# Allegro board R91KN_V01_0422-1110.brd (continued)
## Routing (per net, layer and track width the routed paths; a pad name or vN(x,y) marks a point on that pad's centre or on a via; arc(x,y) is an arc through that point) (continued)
DDC2CLK: length 76.6
  TOP w0.1: U1.AC11 84.95,63.49 v1(85.19,63.73)
  TOP w0.11: v1(72.44,76.25) 72.18,76.5 69.24,76.5 68.61,77.14 67.34,77.14 66.33,78.15 44.13,78.15 35.03,87.25 27.75,87.25 26.15,88.85 25.9,88.85 24.29,87.24 Q1801.2
  BOTTOM w0.11: v1(85.19,63.73) 85.19,63.68 85.53,63.34 85.77,63.34 85.88,63.45 85.88,66.01 84.84,67.05 84.84,67.71 80.34,72.21 78.18,72.21 73.89,76.5 72.7,76.5 v1(72.44,76.25)
DDC2DATA: length 77.8
  TOP w0.1: U1.AC13 84.95,62.55 v1(85.01,62.61)
  TOP w0.11: Q1802.2 24.26,91.09 27.85,87.5 35.13,87.5 44.23,78.4 66.43,78.4 67.44,77.39 68.71,77.39 69.34,76.75 72.18,76.75 v1(72.44,77.01)
  BOTTOM w0.11: v1(72.44,77.01) 72.7,76.75 73.99,76.75 78.28,72.46 80.44,72.46 85.09,67.82 85.09,67.16 86.13,66.12 86.13,63.35 85.88,63.09 85.5,63.09 v1(85.01,62.61)
DDC3CLK: length 99.9
  TOP w0.1: U1.AD20 84.15,56.16 83.88,56.43 83.88,56.95 83.77,57.05 v1(83.77,57.73)
  TOP w0.11: R1008.2 16.89,23.27 19.09,23.27 v1(19.35,23.53) ; v1(27.55,20.26) 27.81,20 31.24,20 33.78,22.54 33.78,27.03 48.4,41.65 72.29,41.65 73.95,43.32 73.95,43.49 v1(73.74,43.7)
  L3_INNER w0.11: v1(83.77,57.73) 83.78,57.73 84.76,56.74 84.76,56.36 84.5,56.1 81.01,56.1 80.32,55.42 74.97,55.42 72.25,52.7 72.25,46.7 74,44.95 74,43.96 v1(73.74,43.7)
  BOTTOM w0.11: v1(19.35,23.53) 19.61,23.27 20.58,23.27 23.85,20 27.29,20 v1(27.55,20.26)
DDC3DATA: length 100.4
  TOP w0.1: U1.AC20 85.02,56 85.34,56.33 85.34,57.55 v1(85.13,57.77)
  TOP w0.11: v1(27.55,19.49) 27.81,19.75 31.34,19.75 33.96,22.37 34.03,22.54 34.03,26.93 48.5,41.4 72.39,41.4 74.2,43.21 74.2,43.45 74.45,43.7 v1(74.51,43.7) ; R1005.2 16.87,23.02 19.09,23.02 v1(19.35,22.76)
  L3_INNER w0.11: v1(85.13,57.77) 84.8,57.43 84.8,57.06 85.01,56.85 85.01,56.26 84.6,55.85 81.11,55.85 80.43,55.17 75.07,55.17 72.5,52.6 72.5,46.8 74.25,45.05 74.25,43.96 v1(74.51,43.7)
  BOTTOM w0.11: v1(27.55,19.49) 27.29,19.75 23.75,19.75 20.48,23.02 19.61,23.02 v1(19.35,22.76)
DDC5CLK_AUX5P: length 84.7
  TOP w0.1: U1.AE16 83.35,59.14 v1(83.19,58.98)
  TOP w0.11: MJ2501.15 11.61,57.91 11.73,58.04 12.74,58.04 13.68,58.98 14.15,58.98 14.73,58.4 14.73,58.75 14.95,58.98 18.68,58.98 19.4,59.7 19.4,60.5 19.65,60.75 21.41,60.75 R2701.2 22.44,60.77 27.59,60.77 32.88,66.05 60.1,66.05 61.72,67.66 v1(62.08,67.66)
  L3_INNER w0.11: v1(62.08,67.66) 61.72,67.66 61.64,67.58 61.64,66.83 61.85,66.62 64.21,66.62 67.59,63.24 68.53,63.24 73.35,58.42 81.54,58.42 81.71,58.6 82.8,58.6 v1(83.19,58.98)
DDC5DATA_AUX5N: length 85.9
  TOP w0.1: v1(83.85,59) 84.15,59.31 U1.AD16
  TOP w0.11: v1(61.54,68.2) 61.54,67.84 60,66.3 32.77,66.3 27.49,61.02 22.44,61.02 R2703.2 21.37,61 19.55,61 19.15,60.6 19.15,59.8 18.57,59.23 14.95,59.23 14.73,59.45 14.73,59.8 14.15,59.23 13.57,59.23 12.64,58.29 11.73,58.29 11.61,58.41 MJ2501.16
  L3_INNER w0.11: v1(83.85,59) 83.19,58.35 81.82,58.35 81.64,58.17 73.25,58.17 68.43,62.99 67.49,62.99 64.11,66.37 61.75,66.37 61.39,66.73 61.39,67.69 61.54,67.84 v1(61.54,68.2)
DDC6CLK: length 41.2
  TOP w0.1: U1.AC1 84.76,69.99 84.76,73.29 80.35,77.7 75.32,77.7 73.3,79.72 73.3,81.75 71.25,83.8 v3(71.25,85.3) ; R4017.2 v3(72.77,97) R4001.1 ; v3(70.7,89.75) 69.99,89.75 R4071.1
  BOTTOM w0.1: v3(72.77,97) 72.77,95.82 71.35,94.4 71.35,90.4 v3(70.7,89.75) 69.61,88.66 69.61,85.74 70.29,85.06 70.95,85.06 71.19,85.3 v3(71.25,85.3)
DDC6DATA: length 41.1
  TOP w0.1: R4002.1 v3(73.91,97.1) R4018.2 ; v3(70.45,85.6) 70.45,84.2 73.1,81.55 73.1,79.64 75.24,77.5 80.27,77.5 84.55,73.22 84.55,69.72 84.95,69.33 U1.AC3 ; v3(70.65,88.5) 70.35,88.5 69.94,88.91 R4070.1
  BOTTOM w0.1: v3(73.91,97.1) 73.91,95.63 71.68,93.39 71.68,89.53 v3(70.65,88.5) 70.65,86.22 70.45,86.03 v3(70.45,85.6)
DDCCLK_DAC1_R: length 7.4
  TOP w0.1: J1601.6 10.74,23.89 11.45,24.6 13.45,24.6 13.98,24.07 D1004.1 R1009.2
DDCCLK_DAC2_R: length 14.3
  TOP w0.1: MJ1001.15 11.13,88.22 12.81,89.9 14.86,89.9 R2009.2
DDCDATA_DAC1_R: length 7.5
  TOP w0.1: J1601.7 9.96,23.2 13.45,23.2 13.98,22.68 D1003.1 R1006.2
DDCDATA_DAC2_R: length 17.7
  TOP w0.1: v3(9.45,86.2) 12.85,89.6 R2006.2
  BOTTOM w0.1: v3(9.45,86.2) 4.61,81.36 MJ1001.12
DPA_0N: length 10.5
  TOP w0.11: C4404.2 21.98,75.22 21.22,75.22 20.97,75.47 20.4,75.47 20.27,75.6 D4401.7 D4401.4 18.43,75.6 18.3,75.47 17.87,75.47 16.69,76.66 16.69,77.14 15.82,78.01 15.4,78.01 15.03,78.38 J2501.3
DPA_0P: length 10.5
  TOP w0.11: C4403.2 21.98,74.97 21.12,74.97 20.87,75.22 20.4,75.22 20.27,75.1 D4401.6 D4401.5 18.43,75.1 18.3,75.22 17.77,75.22 16.44,76.55 16.44,77.04 15.72,77.76 15.4,77.76 15.03,77.38 J2501.1
DPA_1N: length 10.2
  TOP w0.11: C4406.2 21.98,77.22 21.07,77.22 20.82,76.97 20.4,76.97 20.27,77.1 D4401.10 D4401.1 18.43,77.1 18.3,76.97 15.77,79.51 15.4,79.51 15.03,79.88 J2501.6
DPA_1P: length 10.2
  TOP w0.11: J2501.4 15.03,78.88 15.4,79.26 15.67,79.26 18.2,76.72 18.3,76.72 18.43,76.6 D4401.2 D4401.9 20.27,76.6 20.4,76.72 20.92,76.72 21.17,76.97 21.98,76.97 C4405.2
DPA_2N: length 9.8
  TOP w0.11: J2501.9 15.03,81.38 15.4,81.01 16.17,81.01 17.71,79.47 18.3,79.47 18.43,79.6 D4402.4 D4402.7 20.27,79.6 20.4,79.47 20.88,79.47 21.13,79.22 21.98,79.22 C4408.2
DPA_2P: length 9.8
  TOP w0.11: J2501.7 15.03,80.38 15.4,80.76 16.07,80.76 17.6,79.22 18.3,79.22 18.43,79.1 D4402.5 D4402.6 20.27,79.1 20.4,79.22 20.78,79.22 21.03,78.97 21.98,78.97 C4407.2
DPA_3N: length 9.8
  TOP w0.11: J2501.12 15.03,82.88 15.4,82.51 15.99,82.51 17.53,80.97 18.3,80.97 18.43,81.1 D4402.1 D4402.10 20.27,81.1 20.4,80.97 20.62,80.97 20.87,81.22 21.98,81.22 C4410.2
DPA_3P: length 9.8
  TOP w0.11: C4409.2 21.98,80.97 20.98,80.97 20.73,80.72 20.4,80.72 20.27,80.6 D4402.9 D4402.2 18.43,80.6 18.3,80.72 17.42,80.72 15.89,82.26 15.4,82.26 15.03,81.88 J2501.10
DPA_A0N: length 60
  TOP w0.11: U1.AK1 80.03,69.92 80.03,70.44 79.45,71.02 78.88,71.02 78.75,71.15 78.75,71.3 78.62,71.42 78.44,71.42 78.31,71.3 78.31,71.15 78.18,71.02 77.47,71.02 77.04,71.45 71.88,71.45 71.07,72.26 27.53,72.26 24.57,75.22 23.72,75.22 C4404.1
DPA_A0P: length 60
  TOP w0.11: U1.AK3 79.78,69.37 79.78,70.33 79.35,70.77 77.37,70.77 76.93,71.2 71.78,71.2 70.97,72.01 27.43,72.01 24.47,74.97 23.72,74.97 C4403.1
DPA_A1N: length 61.9
  TOP w0.11: C4406.1 23.72,77.22 24.78,77.22 28.76,73.25 78.52,73.25 79.38,72.39 79.56,72.39 79.64,72.47 79.82,72.47 79.95,72.35 79.95,72.16 79.87,72.08 79.87,71.9 80.89,70.87 80.89,69.86 U1.AH1
DPA_A1P: length 61.9
  TOP w0.11: U1.AH3 80.64,69.31 80.64,70.77 78.41,73 28.65,73 24.68,76.97 23.72,76.97 C4405.1
DPA_A2N: length 65.7
  TOP w0.099: 81.81,71.61 81.83,71.6 81.83,71.56 82.25,71.14 82.25,68.71 82.04,68.51 81.84,68.51 81.75,68.42 U1.AG5
  TOP w0.11: 81.81,71.61 79.21,74.21 29.85,74.21 24.84,79.22 23.72,79.22 C4408.1
DPA_A2P: length 65.7
  TOP w0.099: 81.64,71.44 81.66,71.42 81.69,71.42 82.05,71.06 82.05,68.79 81.96,68.71 81.84,68.71 81.75,68.79 U1.AG3
  TOP w0.11: C4407.1 23.72,78.97 24.74,78.97 29.75,73.96 79.11,73.96 80.88,72.2 80.88,72.02 80.68,71.82 80.68,71.64 80.81,71.51 81,71.51 81.19,71.7 81.37,71.7 81.64,71.44
DPA_A3N: length 67.4
  TOP w0.099: U1.AF4 82.55,68.81 82.63,68.89 82.84,68.89 83.05,69.09 83.05,69.98 82.83,70.21 82.83,70.68 82.85,70.71 82.85,70.73
  TOP w0.11: C4410.1 23.72,81.22 24.18,81.22 30.3,75.1 79.94,75.1 82.85,72.19 82.85,70.73
DPA_A3P: length 67.4
  TOP w0.099: U1.AF2 82.55,69.18 82.64,69.09 82.76,69.09 82.85,69.18 82.85,69.9 82.63,70.12 82.63,70.68 82.6,70.71 82.6,70.73
  TOP w0.11: 82.6,70.73 82.6,72.09 82.42,72.26 82.24,72.26 82.06,72.08 81.87,72.08 81.74,72.21 81.74,72.39 81.93,72.57 81.93,72.76 79.83,74.85 30.2,74.85 24.07,80.97 23.72,80.97 C4409.1
DPA_GND: length 9.1
  TOP w0.5: R2715.2 v3(20.35,52.2) ; R2718.2 v3(20.35,55.6) ; R2714.2 v3(20.35,51.2) ; R2716.2 v3(20.35,53.4) ; Q2701.3 21.55,48 20.35,49.2 v3(20.35,50) R2713.2 ; R2719.2 v3(20.35,56.6) ; R2720.2 v3(20.35,57.8) ; R2717.2 v3(20.35,54.4)
DPAB_CALR: length 1.5
  TOP w0.3: U1.AE10 83.35,64.22 v1(82.96,64.62)
  BOTTOM w0.4: R2500.1 83.35,65.01 v1(82.96,64.62)
DPB_0N: length 12
  TOP w0.11: C2531.2 20.68,50.73 19.03,50.73 R2714.1 18.08,50.73 17.62,50.73 17.27,51.08 16.3,51.08 16.17,51.2 D2504.7 D2504.4 14.33,51.2 14.2,51.08 12.93,51.08 12.46,51.54 11.83,51.54 11.45,51.91 MJ2501.3
DPB_0P: length 12
  TOP w0.11: MJ2501.1 11.45,50.91 11.83,51.29 12.36,51.29 12.82,50.83 14.2,50.83 14.33,50.7 D2504.5 D2504.6 16.17,50.7 16.3,50.83 17.17,50.83 17.52,50.48 18.08,50.48 R2713.1 19.03,50.48 20.68,50.48 C2530.2
DPB_1M: length 5.9
  TOP w0.1: J2501.14 17.64,83.88 R2526.1
DPB_1N: length 12
  TOP w0.11: MJ2501.6 11.39,53.41 11.76,53.04 12.77,53.04 13.24,52.58 14.2,52.58 14.33,52.7 D2504.1 D2504.10 16.17,52.7 16.3,52.58 17.3,52.58 17.65,52.92 18.08,52.92 R2716.1 19.03,52.92 20.68,52.92 C2533.2
DPB_1P: length 12
  TOP w0.11: MJ2501.4 11.39,52.41 11.76,52.79 12.67,52.79 13.13,52.33 14.2,52.33 14.33,52.2 D2504.2 D2504.9 16.17,52.2 16.3,52.33 17.4,52.33 17.75,52.67 18.08,52.67 R2715.1 19.03,52.67 20.68,52.67 C2532.2
DPB_2N: length 12.2
  TOP w0.11: MJ2501.9 11.45,54.91 11.83,54.54 12.83,54.54 13.77,55.48 14.2,55.48 14.33,55.6 D2503.4 D2503.7 16.17,55.6 16.3,55.48 17.1,55.48 17.45,55.13 18.08,55.13 R2718.1 19.03,55.12 20.68,55.12 C2536.2
DPB_2P: length 12.2
  TOP w0.11: MJ2501.7 11.45,53.91 11.83,54.29 12.94,54.29 13.87,55.23 14.2,55.23 14.33,55.1 D2503.5 D2503.6 16.17,55.1 16.3,55.23 17,55.23 17.35,54.88 18.08,54.88 R2717.1 19.03,54.88 20.68,54.88 C2534.2
DPB_3N: length 12.2
  TOP w0.11: MJ2501.12 11.45,56.41 11.83,56.04 12.66,56.04 13.59,56.98 14.2,56.98 14.33,57.1 D2503.1 D2503.10 16.17,57.1 16.3,56.98 17,56.98 17.35,57.33 18.08,57.33 R2720.1 19.03,57.32 20.68,57.32 C2538.2
DPB_3P: length 12.2
  TOP w0.11: C2537.2 20.68,57.07 19.03,57.07 R2719.1 18.08,57.08 17.45,57.08 17.1,56.73 16.3,56.73 16.17,56.6 D2503.9 D2503.2 14.33,56.6 14.2,56.73 13.7,56.73 12.76,55.79 11.83,55.79 11.45,55.41 MJ2501.10
DPB_AUXN: length 28
  TOP w0.11: J2501.17 15.03,85.38 15.4,85.01 17.4,85.01 18.1,85.7 18.1,87.6 18.37,87.88 18.6,87.88 18.7,87.88 19.23,88.4 19.23,88 19.35,87.88 21.3,87.88 21.42,88 21.42,89.77 Q1802.3 22.2,90.15 22.45,89.9 22.45,87.2 23.1,86.55 23.85,86.55 24.25,86.15 27.15,86.15 27.58,85.72 29.58,85.72 R2523.2 30.73,85.72 32.18,85.72 C2541.2
DPB_AUXP: length 24
  TOP w0.11: J2501.15 15.05,84.38 15.05,84.4 15.4,84.76 17.51,84.76 18.35,85.6 18.35,87.5 18.48,87.62 18.7,87.62 19.23,87.1 19.23,87.5 19.35,87.62 21.45,87.62 21.81,87.27 Q1801.3 23.75,86.3 24.15,85.9 27.05,85.9 27.48,85.47 29.58,85.47 R2522.1 30.73,85.47 32.18,85.47 C2535.2
DPB_C0N: length 65
  TOP w0.099: 78,66.56 78.03,66.56 78.05,66.53 79.34,66.53 79.63,66.24 79.76,66.24 79.88,66.37 79.88,66.47 U1.AL7
  TOP w0.11: C2531.1 22.42,50.73 25.88,50.73 36.95,61.79 67.41,61.79 71.5,65.89 76.84,65.89 77.51,66.56 78,66.56
DPB_C0P: length 65.1
  TOP w0.099: U1.AK8 79.91,66.04 79.55,66.04 79.26,66.34 78.05,66.34 78.03,66.31 78,66.31
  TOP w0.11: C2530.1 22.42,50.48 25.99,50.48 37.06,61.54 67.51,61.54 71.61,65.64 76.94,65.64 77.61,66.31 78,66.31
DPB_C1N: length 65.5
  TOP w0.099: U1.AH6 80.68,67.13 80.34,67.13 80.26,67.05 80.04,67.05 79.93,67.16 79.91,67.17 79.6,67.17 79.46,67.07 79.38,66.99 78.35,66.99 77.9,67.43 77.57,67.43 77.55,67.46 77.52,67.46
  TOP w0.11: 77.52,67.46 70.89,67.46 66.19,62.76 36.04,62.76 26.2,52.92 22.42,52.92 C2533.1
DPB_C1P: length 65.6
  TOP w0.099: U1.AJ7 80.72,66.77 80.72,66.88 80.67,66.93 80.43,66.93 80.35,66.85 79.96,66.85 79.85,66.96 79.85,66.96 79.83,66.98 79.67,66.98 79.59,66.92 79.46,66.79 78.27,66.79 77.82,67.24 77.57,67.24 77.55,67.21 77.52,67.21
  TOP w0.11: 77.52,67.21 70.99,67.21 66.29,62.51 36.14,62.51 26.31,52.67 22.42,52.67 C2532.1
DPB_C2N: length 64
  TOP w0.099: U1.AM5 79.63,68.2 79.7,68.13 79.7,67.99 79.61,67.9 79.06,67.9 78.87,68.1 78.51,68.1 78.35,68.26 77.77,68.26 77.75,68.29 77.72,68.29
  TOP w0.11: C2536.1 22.42,55.12 26.42,55.12 35.61,64.31 65.2,64.31 69.18,68.29 77.72,68.29
DPB_C2P: length 64
  TOP w0.099: U1.AK6 79.85,67.7 78.98,67.7 78.78,67.9 78.43,67.9 78.26,68.06 77.77,68.06 77.75,68.04 77.72,68.04
  TOP w0.11: 77.72,68.04 69.28,68.04 65.3,64.06 35.71,64.06 26.53,54.88 22.42,54.88 C2534.1
DPB_C3N: length 63.7
  TOP w0.11: C2538.1 22.42,57.32 26.69,57.32 34.87,65.5 64.54,65.5 68.66,69.62 77.98,69.62 78.19,69.42 78.37,69.42 78.55,69.6 78.73,69.6 78.86,69.47 78.86,69.29 78.68,69.11 78.68,68.93 78.84,68.77 79.11,68.77 U1.AM3
DPB_C3P: length 63.8
  TOP w0.11: U1.AK5 79.45,68.52 78.74,68.52 77.88,69.38 68.77,69.38 64.64,65.25 34.97,65.25 26.79,57.07 22.42,57.07 C2537.1
DPB_DONGLE_DET: length 15
  TOP w0.1: J2501.13 15.93,83.38 16.94,82.38 D2502.1 20.02,82.38 R2524.1 24.04,82.61 25.25,81.4 26.15,81.4 Q1804.1
DPCD_CALR: length 21.4
  TOP w0.1: v1(96.5,65.39) 96.5,65.39 96.5,65.39 96.15,65.73 U1.J8
  BOTTOM w0.1: v1(96.5,65.39) 96.54,65.39 96.75,65.6 96.76,65.6 98.37,67.21 98.37,67.38 99.65,68.66 99.65,73.52 99.37,73.8 98.77,73.8 98.25,74.32 98.25,76.78 101.55,80.08 101.55,81.2 101.25,81.5 R298.1
DPE_TX0N: length 70.2
  TOP w0.099: U1.AJ15 80.69,60.06 80.69,59.91 80.59,59.82 80.47,59.82 80.34,59.94 79.98,59.94 79.91,59.87 79.6,59.87 79.5,59.97 77.6,59.97 77.57,59.99 77.55,59.99
  TOP w0.11: 77.55,59.99 77.11,59.99 76.15,59.03 71.82,59.03 69.19,56.4 38.85,56.4 21.88,39.42 20.22,39.42 C1606.1
DPE_TX0P: length 70.2
  TOP w0.099: U1.AH16 80.73,59.62 80.38,59.62 80.26,59.74 80.07,59.74 79.99,59.67 79.52,59.67 79.42,59.77 77.6,59.77 77.57,59.74 77.55,59.74
  TOP w0.11: 77.55,59.74 77.22,59.74 76.25,58.78 71.92,58.78 69.29,56.15 38.95,56.15 21.98,39.17 20.22,39.17 C1605.1
DPE_TX1N: length 70.2
  TOP w0.099: 75.46,58.1 75.49,58.1 75.51,58.08 77.12,58.08 77.92,58.87 79.29,58.87 79.6,59.18 79.93,59.18 U1.AK16
  TOP w0.11: C1604.1 20.22,36.33 20.98,36.33 39.96,55.3 69.45,55.3 72.25,58.1 75.46,58.1
DPE_TX1P: length 70.2
  TOP w0.099: 75.46,57.85 75.49,57.85 75.51,57.88 77.21,57.88 78,58.67 79.37,58.67 79.69,58.98 79.78,58.98 79.91,58.85 79.91,58.76 U1.AL17
  TOP w0.11: C1603.1 20.22,36.08 21.09,36.08 40.06,55.05 69.55,55.05 72.36,57.85 75.46,57.85
DPE_TX2N: length 71.8
  TOP w0.099: 75.34,57.04 75.36,57.04 75.39,57.02 76.85,57.02 78.21,58.38 79.49,58.38 79.62,58.26 79.88,58.26 79.94,58.33 80.36,58.33 80.46,58.22 80.6,58.22 80.7,58.32 80.7,58.45 U1.AJ17
  TOP w0.11: 75.34,57.04 72.38,57.04 69.64,54.3 41.15,54.3 20.92,34.08 20.27,34.08 C1602.1
DPE_TX2P: length 71.7
  TOP w0.099: U1.AH18 80.73,58.02 80.38,58.02 80.28,58.13 80.03,58.13 79.96,58.06 79.54,58.06 79.41,58.18 78.29,58.18 76.93,56.82 75.39,56.82 75.36,56.79 75.34,56.79
  TOP w0.11: 75.34,56.79 72.49,56.79 69.75,54.05 41.25,54.05 21.03,33.83 20.27,33.83 C1601.1
DPE_TXCAN: length 68.7
  TOP w0.099: U1.AK14 79.89,60.74 79.53,60.74 79.32,60.52 79.04,60.52 79.02,60.55 78.99,60.55
  TOP w0.11: 78.99,60.55 77.91,60.55 77.83,60.62 74.36,60.62 73.62,59.89 71.16,59.89 68.92,57.65 37.64,57.65 21.61,41.62 20.22,41.62 C1608.1
DPE_TXCAP: length 68.7
  TOP w0.099: U1.AL15 79.9,60.35 79.9,60.46 79.82,60.54 79.61,60.54 79.4,60.33 79.04,60.33 79.02,60.3 78.99,60.3
  TOP w0.11: C1607.1 20.22,41.38 21.72,41.38 37.74,57.4 69.03,57.4 71.27,59.64 73.73,59.64 74.46,60.38 77.73,60.38 77.8,60.3 78.99,60.3
DPEF_CALR: length 1.9
  TOP w0.3: v1(82.3,57.72) 82.3,58.15 U1.AF17
  BOTTOM w0.3: R1500.1 82.86,58.28 v1(82.3,57.72)
DPEF_GND: length 30.8
  TOP w0.4: v3(18.05,28.7) 18.05,28.7 R1612.1
  TOP w0.5: R1607.1 v3(18.05,40.9) ; v3(18.05,27.5) 18.05,27.5 R1611.1 ; R1614.1 v3(18.05,32.3) ; R1613.1 v3(18.05,31.1) ; Q1601.3 18.08,44.02 18.08,42.13 v3(18.05,42.1) R1608.1 ; R1605.1 v3(18.05,38.7) ; R1601.2 v3(18.05,33.3) ; R1603.1 v3(18.05,35.6) ; R1609.1 v3(18.04,25.3) ; R1610.1 v3(18.04,26.5) ; R1606.1 v3(18.05,39.9) ; R1602.2 v3(18.05,34.6) ; R1604.1 v3(18.05,36.8)
  L3_INNER w0.5: v3(18.04,25.3) v3(18.04,26.5) 18.04,27.49 v3(18.05,27.5) v3(18.05,28.7) v3(18.05,31.1) v3(18.05,32.3) v3(18.05,33.3) v3(18.05,34.6) v3(18.05,35.6) v3(18.05,36.8) v3(18.05,38.7) v3(18.05,39.9) v3(18.05,40.9) v3(18.05,42.1)
DPF_TX3N: length 71
  TOP w0.099: 78.16,56.23 78.19,56.23 78.21,56.2 78.85,56.2 79.18,55.87 79.5,55.87 79.59,55.97 79.92,55.97 U1.AK20
  TOP w0.11: C1614.1 20.22,31.82 21.62,31.82 42.9,53.1 70.29,53.1 71.93,54.73 73.18,54.73 74.67,56.23 78.16,56.23
DPF_TX3P: length 71
  TOP w0.099: U1.AL21 79.91,55.56 79.91,55.65 79.79,55.77 79.67,55.77 79.58,55.67 79.09,55.67 78.77,56 78.21,56 78.19,55.98 78.16,55.98
  TOP w0.11: 78.16,55.98 74.77,55.98 73.28,54.48 72.03,54.48 70.39,52.85 43,52.85 21.73,31.57 20.22,31.57 C1613.1
DPF_TX4N: length 73.1
  TOP w0.099: U1.AJ21 80.67,55.28 80.67,55.14 80.57,55.04 80.44,55.04 80.37,55.12 79.94,55.12 79.87,55.05 79.61,55.05 79.61,55.05 ; 79.2,55.25 79.2,55.25 78.96,55.25 78.69,55.52 78.14,55.52 78.11,55.55 78.09,55.55
  TOP w0.1: 79.61,55.05 79.41,55.25 79.2,55.25
  TOP w0.11: C1612.1 20.22,28.23 20.72,28.23 44.4,51.9 70.83,51.9 72.78,53.84 74.77,53.84 76.47,55.55 78.09,55.55
DPF_TX4P: length 73.1
  TOP w0.099: 78.09,55.3 78.11,55.3 78.14,55.33 78.61,55.33 78.88,55.05 79.2,55.05 79.2,55.05 ; 79.47,54.9 79.49,54.89 79.49,54.89 79.53,54.85 79.7,54.85 79.95,54.85 80.03,54.92 80.28,54.92 80.36,54.84 80.71,54.84 U1.AH22
  TOP w0.1: 79.2,55.05 79.32,55.05 79.47,54.9
  TOP w0.11: C1611.1 20.22,27.98 20.82,27.98 44.5,51.65 70.93,51.65 72.88,53.59 74.87,53.59 76.57,55.3 78.09,55.3
DPF_TX5N: length 72.5
  TOP w0.099: 78.77,54.18 78.79,54.18 78.82,54.15 79.35,54.15 79.55,54.36 79.91,54.36 U1.AK22
  TOP w0.11: 78.77,54.18 76.91,54.18 74.98,52.25 73.18,52.25 71.86,50.93 45.52,50.93 20.62,26.02 20.22,26.02 C1610.1
DPF_TX5P: length 72.5
  TOP w0.099: U1.AL23 79.91,53.96 79.91,54.05 79.8,54.16 79.64,54.16 79.43,53.95 78.82,53.95 78.79,53.93 78.77,53.93
  TOP w0.11: C1609.1 20.22,25.77 20.73,25.77 45.63,50.68 71.96,50.68 73.28,52 75.09,52 77.02,53.93 78.77,53.93
DRAM_RST: length 123.1
  TOP w0.097: U202.T2 138.38,49.03 138.7,49.03 139.03,49.36 139.03,49.44 139.71,50.12 139.71,50.92 139.91,51.13 140.34,51.13 140.52,51.31 140.52,52.72 v1(140.27,52.97) 140.15,53.09 140.15,53.79 140.15,53.89 138.48,55.55 138.48,55.58 138.36,55.7 137.93,55.7 137.18,56.45 137.14,56.45 135.64,57.95 v1(135.64,58.89) 135.59,58.94 135.59,58.94 135.25,59.27 135.25,59.86 135.02,60.09 135.01,60.09 134.75,60.34 134.75,60.44 v1(134.72,60.48) 134.94,60.48 135.15,60.69 135.92,60.69 136.08,60.85 136.38,60.85 v1(136.62,61.1) ; v3(130.78,67.98) 131.08,67.98 131.62,67.43 131.65,67.43 131.93,67.15 131.93,67.06 132.16,66.83 132.5,66.83 132.77,67.1 132.77,67.18 133.37,67.78
  BOTTOM w0.097: v1(140.27,52.97) 140.23,52.97 139.58,53.62 137.7,53.62 137.51,53.44 136.13,53.44 133.31,50.62 133.31,48.87 133.37,48.81 ; v3(130.78,67.98) 130.79,67.98 130.79,68.03 131.01,67.82 131.01,66.95 130.91,66.86 130.91,66.34 130.94,66.31 130.94,65.66 130.72,65.43 130.72,64.81 132.97,62.55 132.97,62.25 133.47,61.76 133.47,61.22 134.02,60.67 134.51,60.67 v1(134.72,60.48) ; U402.T2 138.16,67.61 139.55,66.23 139.55,63.06 137.58,61.09 137.24,61.09 137.08,61.25 136.78,61.25 v1(136.62,61.1)
  BOTTOM w0.1: R3616.1 108.08,85.32 119.45,85.32 v4(120.38,86.25) 120.89,86.77 140.31,86.77 145.25,81.83 145.25,66.5 144.15,65.39 142.5,65.39 141.69,64.59 141.69,61.35 141.18,60.84 141.18,60.78 140.36,59.97 140.35,59.97 139.88,59.5 139.03,59.5 138.42,58.89 v1(135.64,58.89)
DRST: length 27.6
  TOP w0.1: v1(94.95,64.56) 94.59,64.2 U1.L10
  BOTTOM w0.1: v1(94.95,64.56) 95.3,64.21 95.98,64.21 96.07,64.12 96.66,64.12 96.96,64.42 96.96,65.52 98.57,67.13 98.59,67.13 98.59,67.31 99.85,68.58 99.85,73.6 99.45,74 98.85,74 98.45,74.4 98.45,76.7 99.15,77.4 99.75,77.4 101.85,79.5 101.85,82.11 R3600.2 C3600.1 104.24,83.49 R3615.2
DRST_R: length 2
  BOTTOM w0.1: R3616.2 C3608.1 R3615.1
EFTX0M: length 19.9
  TOP w0.099: 5.75,34 5.75,33.98 5.78,33.95 5.78,32.75 5.62,32.6 5.12,32.6 4.93,32.79 J1601.17
  TOP w0.11: 5.75,34 5.75,35.3 10.21,39.76 12.67,39.76 12.79,39.89 D1602.4 D1602.7 14.64,39.89 14.76,39.76 15.24,39.76 15.58,39.42 15.88,39.42 R1606.2 16.83,39.42 18.28,39.42 C1606.2
EFTX0P: length 19.8
  TOP w0.099: 6,34 6,33.98 5.97,33.95 5.97,32.67 5.71,32.4 5.12,32.4 4.93,32.21 J1601.18
  TOP w0.11: C1605.2 18.28,39.17 16.83,39.17 R1605.2 15.88,39.17 15.48,39.17 15.14,39.51 14.76,39.51 14.64,39.39 D1602.6 D1602.5 12.79,39.39 12.67,39.51 10.31,39.51 6,35.2 6,34
EFTX1M: length 15.7
  TOP w0.099: 7.67,33.98 7.67,33.95 7.7,33.93 7.7,32.83 7.46,32.59 7.01,32.59 6.84,32.76 J1601.9
  TOP w0.11: 7.67,33.98 7.67,34.19 9.4,35.93 12.67,35.93 12.79,36.05 D1600.1 D1600.10 14.64,36.05 14.76,35.93 14.98,35.93 15.38,36.33 15.88,36.33 R1604.2 16.83,36.33 18.28,36.33 C1604.2
EFTX1P: length 15.7
  TOP w0.099: J1601.10 6.84,32.19 7.04,32.39 7.54,32.39 7.89,32.74 7.89,33.93 7.92,33.95 7.92,33.98
  TOP w0.11: C1603.2 18.28,36.08 16.83,36.08 R1603.2 15.88,36.08 15.48,36.08 15.08,35.68 14.76,35.68 14.64,35.55 D1600.9 D1600.2 12.79,35.55 12.67,35.68 9.51,35.68 7.92,34.09 7.92,33.98
EFTX2M: length 12
  TOP w0.11: C1602.2 18.23,34.08 16.88,34.08 R1602.1 15.83,34.08 15.48,34.08 15.12,34.43 14.76,34.43 14.64,34.55 D1600.7 D1600.4 12.79,34.55 12.67,34.43 11.98,34.43 10.14,32.59 9.57,32.59 J1601.1
EFTX2P: length 12
  TOP w0.11: J1601.2 9.57,32.34 10.24,32.34 12.08,34.18 12.67,34.18 12.79,34.05 D1600.5 D1600.6 14.64,34.05 14.76,34.18 15.02,34.18 15.37,33.83 15.83,33.83 R1601.1 16.88,33.83 18.25,33.83 18.76,33.32 C1601.2
EFTX3M: length 17.5
  TOP w0.099: 9.04,30.68 9.03,30.68 9,30.65 8.1,30.65 7.7,30.24 7.7,27.12 7.42,26.85 7.03,26.85 6.84,27.04 J1601.12
  TOP w0.11: C1614.2 18.28,31.82 16.83,31.82 R1614.2 15.88,31.82 15.32,31.82 15.03,32.12 14.76,32.12 14.64,32.24 D1603.5 D1603.6 12.79,32.24 12.67,32.12 11.27,32.12 9.83,30.68 9.04,30.68
EFTX3P: length 17.5
  TOP w0.099: 9.04,30.43 9.02,30.43 8.99,30.45 8.18,30.45 7.89,30.16 7.89,27.04 7.5,26.65 7.02,26.65 6.84,26.46 J1601.13
  TOP w0.11: 9.04,30.43 9.93,30.43 11.37,31.87 12.67,31.87 12.79,31.74 D1603.7 D1603.4 14.64,31.74 14.76,31.87 14.93,31.87 15.22,31.57 15.88,31.57 R1613.2 16.83,31.57 18.28,31.57 C1613.2
EFTX4M: length 12.1
  TOP w0.11: C1612.2 18.28,28.23 16.83,28.23 R1612.2 15.88,28.23 15.57,28.23 15.1,27.75 15.1,27.35 14.95,27.2 14.76,27.2 14.64,27.33 D1601.10 D1601.1 12.79,27.33 12.67,27.2 12.4,27.2 11.76,26.57 10.36,26.57 10.06,26.87 9.57,26.87 J1601.4
EFTX4P: length 12.1
  TOP w0.11: C1611.2 18.28,27.98 16.83,27.98 R1611.2 15.88,27.98 15.68,27.98 15.35,27.65 15.35,27.25 15.05,26.95 14.76,26.95 14.64,26.83 D1601.9 D1601.2 12.79,26.83 12.67,26.95 12.5,26.95 11.87,26.32 10.26,26.32 9.96,26.62 9.57,26.62 J1601.5
EFTX5M: length 17.2
  TOP w0.099: J1601.20 4.93,27 5.08,26.85 5.67,26.85 5.96,26.55 5.96,25.43 6.45,24.94 9.5,24.94 9.53,24.97 9.55,24.97
  TOP w0.11: C1610.2 18.28,26.02 16.83,26.02 R1610.2 15.88,26.02 15.48,26.02 15.15,25.7 14.76,25.7 14.64,25.83 D1601.7 D1601.4 12.79,25.83 12.67,25.7 10.55,25.7 9.81,24.97 9.55,24.97
EFTX5P: length 17.2
  TOP w0.099: 9.55,24.72 9.53,24.72 9.5,24.74 6.37,24.74 5.77,25.35 5.77,26.47 5.58,26.65 5.06,26.65 4.93,26.52 J1601.21
  TOP w0.11: 9.55,24.72 9.92,24.72 10.65,25.45 12.67,25.45 12.79,25.33 D1601.5 D1601.6 14.64,25.33 14.76,25.45 15.26,25.45 15.58,25.77 15.88,25.77 R1609.2 16.83,25.77 18.28,25.77 C1609.2
EFTXCM: length 34.2
  TOP w0.11: J1601.24 4.31,20.7 3.93,20.7 3.41,21.23 3.41,34.42 10.25,41.26 12.67,41.26 12.79,41.39 D1602.1 D1602.10 14.64,41.39 14.76,41.26 15.06,41.26 15.42,41.62 15.88,41.62 R1608.2 16.83,41.62 18.28,41.62 C1608.2
EFTXCP: length 34.3
  TOP w0.11: J1601.23 5.13,21.79 5.13,21.26 4.83,20.95 4.04,20.95 3.66,21.34 3.66,34.32 10.35,41.01 12.67,41.01 12.79,40.89 D1602.2 D1602.9 14.64,40.89 14.76,41.01 15.16,41.01 15.52,41.38 15.88,41.38 R1607.2 16.83,41.38 18.28,41.38 C1607.2
FANOUT_N: length 8.4
  TOP w0.503: 163.55,18.82 JU4001.2 ; JU4001.2 164.31,18.58 ; JU4001.2 165.06,18.82 ; JU4001.2 165.31,19.58 ; JU4001.2 163.88,18.6 ; JU4001.2 165.29,20 ; JU4001.2 163.31,19.58 ; JU4001.2 163.32,19.16
FANOUT_P: length 9.2
  TOP w0.503: 163.31,21.58 JU4001.1 ; JU4001.1 165.31,21.58 ; JU4001.1 165.31,22.08 ; JU4001.1 164.31,22.58 ; JU4001.1 163.31,21.08 ; JU4001.1 165.31,22.58 ; JU4001.1 163.31,22.58 ; JU4001.1 164.81,22.58
G1_PMBUS_C: length 1.4
  TOP w0.1: R597.2 84.35,85.3 TP502.1
G1_PMBUS_D: length 1.3
  TOP w0.1: R596.2 TP501.1
G_DAC2: length 56.7
  TOP w0.155: v3(23.45,22.1) 23.09,22.1 MR1016.2 ; v3(10.35,66.9) C2002.1 R2002.1 9.15,68.29 L2002.1
  BOTTOM w0.155: v3(10.35,66.9) 10.68,66.57 11.05,66.57 11.43,66.19 11.43,64.42 13.58,62.27 13.58,31.17 16.26,28.49 16.26,26.09 17.65,24.7 20.85,24.7 v3(23.45,22.1)
GB_DAC2: length 54.5
  TOP w0.155: MR1028.2 23.64,21.49 v3(23.45,21.3) ; R2028.1 v3(10.34,66)
  BOTTOM w0.155: v3(10.34,66) 10.61,66.27 10.92,66.27 11.13,66.07 11.13,64.3 13.28,62.15 13.28,31.05 15.96,28.37 15.96,25.97 17.53,24.4 20.73,24.4 22.87,22.26 22.87,21.88 v3(23.45,21.3)
GENERICA: length 19.9
  TOP w0.1: v1(84.96,61.38) 84.96,61.38 84.96,61.37 85.01,61.42 85.73,61.42 U1.AB13
  BOTTOM w0.1: v1(84.96,61.38) 84.96,61.38 84.96,61.39 84.4,61.95 84.28,61.95 83.82,62.41 83.82,64.16 84.07,64.41 84.07,66.02 82.94,67.16 82.94,67.79 81.92,68.8 81.26,68.8 78.94,71.12 76.15,71.12 v4(74.68,69.65) 74.68,68.64 R73.2
GENERICB: length 6.3
  TOP w0.1: U1.W8 88.72,66.17 88.87,66.17 v1(88.94,66.24)
  BOTTOM w0.1: R32.2 89.38,69.68 89.38,66.7 88.94,66.26 v1(88.94,66.24)
GENERICC: length 2.8
  TOP w0.1: U1.W9 88.25,65 v1(87.86,65.39)
  BOTTOM w0.1: TP58.1 89.28,64.54 89.1,64.36 88.82,64.36 87.86,65.32 v1(87.86,65.39)
GENERICD: length 2.9
  TOP w0.1: U1.W7 87.89,66.6 v1(87.76,66.47)
  BOTTOM w0.1: v1(87.76,66.47) 87.91,66.62 TP59.1
GENERICE_HPD4: length 125.9
  TOP w0.1: v3(84,72.59) 84.35,72.24 84.35,69.64 84.56,69.43 84.56,66.37 84.38,66.19 83.97,66.19 83.77,65.99 83.77,64.58 U1.AD10 ; v3(60.07,40.77) 48.72,40.77 34.95,27 34.95,22.1 32.25,19.4 v3(32.25,18.4)
  BOTTOM w0.1: Q1602.2 31.05,18.6 R1617.1 32.25,18.29 v3(32.25,18.4) ; v3(60.07,40.77) 60.07,65.68 59.85,65.91 59.85,74.9 64.84,79.89 64.84,84.84 66,86 67.91,86 71.89,82.02 71.89,80.56 71.89,80.23 78.76,73.36 83.24,73.36 v3(84,72.59)
GPIO_0: length 30.6
  TOP w0.1: U1.U6 89.75,67.48 88.94,68.28 88.79,68.34 88.54,68.58 88.54,69.03 88.42,69.16 88.42,69.6 88.98,70.16 88.98,72.33 89.8,73.15 89.8,78.86 R45.2 89.08,81.04 v3(89.08,81.28)
  BOTTOM w0.1: SW4001.1 97.55,89.65 97.55,86 96.15,84.6 91.79,84.6 89.08,81.89 v3(89.08,81.28)
GPIO_1: length 32.9
  TOP w0.1: v1(90.17,64.49) 89.88,64.2 U1.U10
  BOTTOM w0.1: v1(90.17,64.49) 90.17,64.49 90.17,64.49 90.75,65.07 90.75,67.25 90.98,67.48 90.98,72.72 88.11,75.59 88.11,77.01 87.82,77.3 87.82,80.37 88.65,81.2 88.65,81.77 92.41,85.52 93.76,85.52 R46.2 96.44,87.2 96.62,87.38 96.62,88.42 96.12,88.91 SW4001.2
GPIO_2: length 30.8
  TOP w0.1: U1.T10 90.75,64.47 90.15,65.07 v1(90.15,65.25)
  BOTTOM w0.1: v1(90.15,65.25) 90.55,65.65 90.55,66.3 90.27,66.58 90.06,66.58 89.79,66.85 89.79,67.41 90.55,68.17 90.55,72.7 89.23,74.02 89.23,74.19 87.91,75.51 87.91,76.86 87.62,77.15 87.62,78.78 87.23,79.18 87.23,80.06 88.45,81.28 88.45,81.9 92.02,85.47 92.02,86.61 MR47.2 R47.2 92.14,87.64 92.14,89.4 SW4002.1
GPIO_3_SMBDATA: length 111.2
  TOP w0.1: U1.U8 89.35,65.6 89.03,65.6 89.02,65.59 v1(88.92,65.59) ; v3(59.46,39.88) 58.72,39.14 58.72,32.26 58.01,31.55 58.01,21.65 Q1.2 54.66,18.29 R1.2 54.45,16.59 R3.1
  BOTTOM w0.1: v3(59.46,39.88) 59.46,74.8 64.64,79.97 64.64,84.92 65.92,86.2 67.99,86.2 72.09,82.11 72.09,80.47 72.09,80.31 78.83,73.56 83.87,73.56 83.96,73.47 84.82,73.47 87.12,71.17 87.12,70.16 88.42,68.86 88.42,68.33 88.14,68.05 88.14,67.42 88.44,67.12 88.44,65.91 88.77,65.59 v1(88.92,65.59)
GPIO_4_SMBCLK: length 112.6
  TOP w0.1: U1.U7 89.27,66.88 v1(88.91,66.88) ; v3(58.53,39.87) 58.14,39.49 58.14,32.69 57.55,32.1 57.55,23.3 56.6,22.35 53.9,22.35 53.21,21.66 Q2.2 53.21,19.97 R2.2 52.35,17.11 R4.1
  BOTTOM w0.1: v3(58.53,39.87) 58.53,41.26 58.55,41.28 58.55,74.17 64.44,80.06 64.44,85 65.83,86.4 68.08,86.4 72.29,82.19 72.29,80.39 78.92,73.76 83.95,73.76 84.04,73.67 84.78,73.67 84.85,73.74 87.35,71.25 87.35,70.3 89.09,68.56 89.09,67.05 v1(88.91,66.88)
GPIO_5: length 8.5
  TOP w0.1: U1.T9 90.58,65.17 90.58,65.45 90.38,65.65 90.38,65.79 v1(90.04,66.13)
  BOTTOM w0.1: v1(90.04,66.13) 89.57,66.59 89.57,67.48 90.35,68.26 90.35,71.3 89.66,71.99 R54.2
GPIO_6: length 18.9
  TOP w0.1: U1.T8 90.75,66.08 90.26,66.57 90.04,66.57 89.9,66.71 89.9,66.75 89.84,66.81 89.84,66.88 89.32,67.39 89.32,67.62 88.84,68.1 88.63,68.16 88.09,68.7 87.95,68.7 87.78,68.87 87.78,69.78 87.36,70.2 87.36,71 89.6,73.24 89.6,77.53 89.13,78 88.05,78 87.75,78.31 87.75,79.39 MR58.2
GPIO_7: length 33.2
  TOP w0.1: U1.T7 90.85,66.7 90.85,67.52 90.52,67.86 89.67,67.86 89.44,68.09 89.44,68.58 88.91,69.1 88.83,69.1 88.65,69.28 88.65,69.52 89.18,70.05 89.18,72.13 90,72.95 90,80.99 89.18,81.81 80.44,81.81 77.75,84.5 76.11,84.5 MR57.1
GPIO_8_R: length 4.2
  TOP w0.1: MR53.2 R13.2 R53.2 81.1,90.6 81.74,91.23 U2.2
GPIO_8_SO: length 39.4
  TOP w0.1: v3(92.38,81.89) 90.56,83.7 83.85,83.7 83.45,84.1 83.45,86.1 82.65,86.9 79.53,86.9 78.73,87.7 78.73,88.88 R13.1 ; U1.P10 91.95,64.48 91.5,64.93 91.5,65.82 91.45,65.86 91.45,66.01 v1(91.37,66.1)
  BOTTOM w0.1: v1(91.37,66.1) 91.37,66.1 90.99,66.48 90.99,67.21 91.18,67.4 91.18,72.81 89.99,74 89.99,79.78 92.1,81.89 v3(92.38,81.89)
GPIO_9_R: length 5.3
  TOP w0.1: R14.2 89.26,86.3 R44.2 MR44.2 89.55,88.01 89.55,88.57 89.42,88.69 U2.5
GPIO_9_SI: length 19.7
  TOP w0.1: R14.1 93.34,82.61 93.34,77.02 91.82,75.49 91.82,69.8 91.63,69.61 91.63,69.19 92.15,68.67 U1.P4
GPIO_10_R: length 2.1
  TOP w0.1: U2.6 89.51,89.97 89.78,89.69 R15.2
GPIO_10_SCK: length 21.4
  TOP w0.1: U1.P2 92.23,69.48 92.23,75.34 93.83,76.93 93.83,84.87 90.45,88.24 R15.1
GPIO_11: length 24.2
  TOP w0.1: R48.2 96.57,89.33 96.57,87.2 95.43,86.06 95.43,79.5 94.65,78.72 94.65,76.63 93.09,75.07 93.09,70.3 93.25,70.14 93.25,67.7 U1.N6
GPIO_12: length 23
  TOP w0.1: MR50.2 93.34,89.29 93.34,86.76 94.05,86.05 94.05,76.88 92.43,75.26 92.43,69.58 92.63,69.37 92.63,68.87 92.95,68.55 U1.N5
GPIO_13: length 21.9
  TOP w0.1: U1.N3 92.95,69.34 92.63,69.66 92.63,75.18 94.25,76.79 94.25,86.13 94.31,86.2 94.31,89.05 MR49.2
GPIO_14_HPD2: length 90.5
  TOP w0.1: v1(86.56,65) 86.56,65 U1.Y9 ; R2530.1 16.75,72.44 Q2513.2 18.06,69.65 18.69,69.01 19.74,69.01 21.67,70.94 22.48,70.94 23.01,70.41 23.01,69.75 23.77,68.99 24.41,68.99 24.82,68.58 60.88,68.58 v3(62.18,69.88)
  BOTTOM w0.1: v3(62.18,69.88) 62.18,75.18 65.38,78.38 66.17,78.38 67.08,77.47 69.09,77.47 69.77,76.78 71.53,76.78 72.54,77.8 73.63,77.8 78.36,73.08 80.34,73.08 85.34,68.07 85.34,67.34 86.16,66.52 86.16,66.51 86.4,66.28 86.4,66.28 86.56,66.12 v1(86.56,65)
GPIO_15_PWRCNTL_0: length 54.7
  TOP w0.1: U1.N1 92.89,69.86 92.89,75.15 94.45,76.71 94.45,78.8 95.23,79.59 95.23,86.7 95.58,87.05 95.58,89.34 R1240.1 MR1240.2 95.55,90.29 95.55,92.84 94.79,93.6 91.26,93.6 83.56,101.3 v3(76.65,101.3)
  BOTTOM w0.1: Q1200.1 71.43,103.72 73,102.15 75.8,102.15 v3(76.65,101.3)
GPIO_16: length 23.9
  TOP w0.1: U1.M4 94.06,68.92 94.06,69.54 93.95,69.65 93.95,70.38 93.7,70.64 93.7,73.39 94.68,74.37 94.68,75.81 95.25,76.38 95.25,78.47 96.03,79.26 96.03,80.28 98.85,83.09 98.85,89.19 MR55.2
GPIO_17_THERMINT: length 50.3
  TOP w0.1: R4080.1 R4401.2 R4011.2 v3(75.06,96.89) ; v3(72.85,93.6) 72.01,92.76 72.01,89.64 73.01,88.64 73.01,87.54 73.76,86.79 76.21,86.79 80.66,82.35 89.92,82.35 90.22,82.05 90.22,72.89 89.46,72.12 89.46,69.93 89.45,69.92 89.45,69.9 89.41,69.87 89.41,68.91 89.69,68.64 89.78,68.64 90.33,68.08 90.67,68.08 U1.R6
  BOTTOM w0.1: v3(72.85,93.6) 75.06,95.81 v3(75.06,96.89)
GPIO_18_HPD3: length 1.5
  TOP w0.1: v1(87.75,64.7) 87.85,64.7 U1.W10
  BOTTOM w0.1: TP97.1 v1(87.75,64.7)
GPIO_19_CTF: length 53.1
  TOP w0.1: R4400.2 105.88,107.87 106.65,107.1 106.65,106.2 109.14,103.71 109.14,96.1 R4062.1 108.65,94.63 107.7,93.68 106.12,93.68 105.59,94.21 101.67,94.21 100.25,92.78 R4038.1 99.31,92.09 98.84,92.56 98.06,92.56 97.75,92.25 97.75,82.28 95.83,80.36 95.83,79.34 95.05,78.55 95.05,76.46 93.5,74.91 93.5,70.56 93.75,70.3 U1.M2
GPIO_20_PWRCNTL_1: length 52.8
  TOP w0.1: R1241.1 81.91,85.94 81.45,86.4 79.55,86.4 78.35,87.6 78.35,90 77.95,90.4 v3(77.95,100.71) ; MR1241.2 82.97,83.39 90.01,83.39 90.19,83.39 91.9,81.68 91.9,76.45 91.9,76.45 91.9,76.42 91.22,75.74 91.22,70.54 90.84,70.16 90.84,69.59 90.88,69.54 90.88,69.02 91.29,68.61 91.39,68.61 91.66,68.33 91.66,67.42 92.32,66.76 92.32,66.17 U1.P8
  BOTTOM w0.1: Q1201.1 75.43,104.17 77.95,101.65 v3(77.95,100.71)
GPIO_21: length 3.3
  TOP w0.1: v1(91.39,66.82) 91.38,66.82 91.38,66.82 91.6,66.6 U1.P7
  BOTTOM w0.1: TP94.1 91.38,68.53 91.38,67.07 91.39,67.06 91.39,66.92 91.38,66.91 91.38,66.82 v1(91.39,66.82)
GPIO_22_CS: length 38.4
  TOP w0.1: U1.N8 93.15,66.07 92.61,66.61 92.61,68.56 92.09,69.08 92.04,69.08 91.85,69.28 91.85,69.55 92.02,69.72 92.02,75.42 93.63,77.02 93.63,84.32 89.84,88.11 89.84,88.75 89.2,89.38 87.38,89.38 83.46,93.29 80.54,93.29 79.65,92.4 R16.1
GPIO_22_ROMCSB_R: length 3.5
  TOP w0.1: R16.2 R24.1 81.16,91.5 82.17,92.5 U2.1
GPIO_23: length 18.7
  TOP w0.1: U1.N7 93.45,66.9 93.45,70.23 93.29,70.38 93.29,74.99 94.85,76.54 94.85,78.64 95.63,79.42 95.63,82.27 TP91.1
GPU_DMINUS: length 33.7
  TOP w0.125: U1.T2 90.62,69.47 90.62,70.37 90.95,70.7 90.95,75.8 91.69,76.54 91.69,81.59 90.1,83.18 80.97,83.18 76.1,88.05 76.1,88.86 C4004.2 76.05,89.59 76.05,89.95 76.15,90.05 U4001.4
GPU_DPLUS: length 34.6
  TOP w0.1: 90.32,69.77 90.32,69.62 90.23,69.53 90.23,69.28 90.55,68.96 U1.T4
  TOP w0.125: U4001.3 75.65,90.05 75.75,89.95 75.75,89.49 C4004.1 75.8,88.86 75.8,87.93 80.85,82.88 89.97,82.88 91.39,81.47 91.39,76.66 90.65,75.92 90.65,70.82 90.32,70.5 90.32,69.77
HPD1: length 68.7
  TOP w0.1: Q4402.2 24.12,70.19 R4409.1 60.92,70.19 61.59,70.87 70.76,70.87 70.97,70.66 v3(76.5,70.66) ; U1.AC14 84.85,60.8 v1(84.25,61.4)
  BOTTOM w0.1: v3(76.5,70.66) 77.63,70.66 77.88,70.92 78.84,70.92 81.15,68.6 81.84,68.6 82.73,67.71 82.73,67.07 83.87,65.94 83.87,64.5 83.62,64.24 83.62,62.32 84.25,61.69 v1(84.25,61.4)
HPD1_A: length 7.8
  TOP w0.1: R4410.2 16.06,62 15.05,62 14.73,61.67 14.73,61.4 12.75,61.4 11.27,59.91 MJ2501.19
HPD4_IN: length 1.6
  BOTTOM w0.1: Q1602.1 33.09,17.35 R1618.1
HPD_DPB: length 16.7
  TOP w0.1: v3(17.35,85.7) 16.98,86.08 D4405.1 15.86,85.88 J2501.18 ; v3(18.25,74.3) 18.79,73.76 R2527.2
  BOTTOM w0.1: v3(18.25,74.3) 18.25,74.7 17.35,75.6 v3(17.35,85.7)
HPD_DVIEF: length 38.2
  BOTTOM w0.1: J1601.16 4.75,17.99 4.75,16.5 5.26,15.99 5.26,15.29 4.65,14.68 4.65,13.69 5.46,12.88 9.86,12.88 10.92,13.94 11.76,13.94 12.06,13.64 19.69,13.64 20.58,14.53 30.48,14.53 32.26,16.31 R1618.2
JTAG_TCK: length 89.7
  TOP w0.1: v3(89.71,81.91) 89.55,82.07 80.59,82.07 76.15,86.51 73.56,86.51 72.67,87.4 68.92,87.4 v3(66.94,85.41) ; v3(101.75,92.63) 101.75,87.72 v3(100.3,86.28) 100.3,81.99 96.75,78.44 96.75,77.43 94.88,75.56 94.88,74.29 93.93,73.34 93.93,70.69 94.15,70.47 94.15,69.74 94.55,69.34 U1.L3
  BOTTOM w0.1: 101.75,91.08 v3(101.75,92.63) ; v3(66.94,85.41) 65.35,83.83 65.35,79.6 61.04,75.29 61.04,69.47 61.17,69.34 62.55,69.34 63.89,70.67 NR75.2 ; v3(89.71,81.91) 91.59,83.79 97.81,83.79 v3(100.3,86.28)
JTAG_TDI: length 29.9
  TOP w0.1: v3(104.19,92.35) 104.15,92.31 104.15,85.1 97.35,78.3 97.35,77.46 95.28,75.39 95.28,74.13 94.33,73.17 94.33,70.91 94.55,70.69 94.55,70.24 94.87,69.93 94.87,69.66 94.84,69.63 94.84,69.17 94.87,69.13 94.87,68.86 94.55,68.54 U1.L5
  BOTTOM w0.1: v3(104.19,92.35) 104.28,92.26 104.28,91.08
JTAG_TDO: length 29.5
  TOP w0.099: 95.68,70.38 95.64,70.09
  TOP w0.1: U1.K4 95.46,69.07 95.66,69.27 95.66,69.53 95.64,69.6 95.64,69.63 95.64,70.08 95.64,70.09 ; 95.68,70.38 95.68,75.23 97.92,77.47 97.92,78.19 105.55,85.83 105.55,92.04 v3(105.87,92.35)
  BOTTOM w0.1: v3(105.87,92.35) 105.55,92.04 105.55,91.09 105.56,91.08
JTAG_TMS: length 27.7
  TOP w0.1: U1.L1 94.35,70 94.35,70.55 94.13,70.78 94.13,73.25 95.08,74.21 95.08,75.48 96.95,77.35 96.95,78.23 103.02,84.3 v3(103.02,92.35)
  BOTTOM w0.1: v3(103.02,92.35) 103.02,91.08
JTAG_TRSTB: length 29.6
  TOP w0.1: R38.2 R39.1 104.45,90.29 104.45,85.12 97.65,78.32 97.65,77.48 95.48,75.31 95.48,74.04 94.53,73.09 94.53,71.02 94.75,70.79 94.75,70.32 95.06,70.01 95.06,69.57 95.03,69.54 95.03,69.23 95.06,69.19 95.06,68.77 94.87,68.57 94.87,67.72 U1.L6
JTDIO_LOOP: length 8.7
  BOTTOM w0.15: MPCIE1.A7 51.65,5.9 51.8,6.05 51.8,7.05 51.45,7.4 50.92,7.4 50.62,7.1 50.62,3.52 MPCIE1.A6
LDO1_FB: length 5.8
  BOTTOM w0.5: R864.1 R865.2 C865.2 54.84,34.49 54.25,33.9 53.75,33.9 53.07,33.22 U861.7
LDO1_REFIN: length 2
  BOTTOM w0.5: R866.2 50.5,32.59 U861.5
LDO2_FB: length 4.3
  BOTTOM w0.5: U851.7 50.88,43.97 R854.1 52.34,43.69 R855.2 C855.2
LED: length 2.9
  TOP w0.1: D4000.1 Q4050.3
LED_ON: length 1.9
  TOP w0.1: Q4050.1 90.92,97.81 R4058.1
LED_PWR: length 2.4
  TOP w0.1: R4059.1 92.03,106.46 D4000.2
LM63_PWM: length 1.5
  TOP w0.1: U4001.5 77.68,89.49 R4081.1
M_DQMA#0: length 63.2
  TOP w0.1: U1.E32 99.35,47.55
  TOP w0.12: U202.E7 134.18,40.01 134.83,40.01 135.17,40.34 135.17,41.78 ; 99.35,47.55 99.35,47.55 100.61,46.28 100.62,46.28 100.63,46.28 100.97,46.28 100.97,46.28 101.69,46.28 102.33,45.64 102.33,45.38 102.34,45.37 v1(102.34,45.36) ; 134.37,42.86 131.87,42.86 131.13,43.59 129.16,43.59 128.9,43.84 v4(128.42,43.84) 127.57,43.84 125.59,45.83 112.8,45.83 109.49,49.14 105.48,49.14 v1(105.25,48.92)
  TOP w0.13: 135.17,41.78 135.17,42.05 134.37,42.86
  BOTTOM w0.12: v1(102.34,45.36) 102.12,45.36 101.98,45.49 101.98,48.19 101.86,48.3 101.06,48.3 100.94,48.18 100.94,48.05 100.81,47.92 100.23,47.92 100.11,48.05 100.11,49.28 100.01,49.38 99.91,49.38 99.78,49.51 99.78,49.66 100.03,49.9 100.58,49.9 100.7,49.78 100.7,48.98 100.83,48.86 101.06,48.86 101.18,48.98 101.18,49.78 101.3,49.9 101.54,49.9 101.66,49.78 101.66,49.17 101.84,49 102.02,49 102.14,49.12 102.14,49.78 102.26,49.9 102.5,49.9 102.62,49.78 102.62,48.63 102.75,48.51 102.92,48.51 103.05,48.63 103.05,49.77 103.17,49.9 103.37,49.9 103.49,49.77 103.49,48.59 103.62,48.47 103.82,48.47 103.95,48.59 103.95,50.21 104.07,50.34 104.29,50.34 104.41,50.21 104.41,49.22 104.54,49.09 105.13,49.09 105.25,48.97 v1(105.25,48.92)
M_DQMA#1: length 66.4
  TOP w0.12: U1.E30 99.22,49 99.1,48.88 99.1,48.73 99.26,48.56 99.57,48.56 99.7,48.44 99.7,47.74 100.1,47.34 100.1,47.34 100.34,47.09 100.68,47.09 100.69,47.1 101.18,47.1 102.51,45.77 102.75,45.53 102.75,45.19 102.67,45.11 102.67,44.73 102.69,44.72 102.69,44.63 102.58,44.52 101.53,44.52 101.41,44.4 101.41,43.99 101.54,43.87 102.27,43.87 v4(102.32,43.91) 102.37,43.91 102.55,43.73 102.55,43 102.44,42.88 101.55,42.88 101.42,42.76 101.42,42.48 101.55,42.36 102.55,42.36 102.67,42.23 102.67,42 102.55,41.88 101.59,41.88 101.47,41.75 101.47,41.42 101.46,41.42 101.46,39.38 106.39,34.46 106.78,34.46 108.08,33.16 122.65,33.16 124.38,31.43 134.94,31.43 137.96,34.45 138.61,34.45 138.84,34.67 138.84,34.67 139.56,35.38 139.56,35.39 140.12,35.96 140.12,37.23 140.13,37.24 140.13,37.58 139.89,37.82 139.36,37.82 139.16,38.02 138.87,38.02 138.56,38.32 138.56,38.51 138.22,38.86 137.75,38.86 137.4,39.22 137.37,39.22
M_DQMA#2: length 66
  TOP w0.099: U1.A21 100.95,55.4 102.41,55.4 102.48,55.32
  TOP w0.12: 102.48,55.32 104.2,55.32 105.37,54.15 109.55,54.15 112.04,51.66 112.04,50.91 113.48,49.47 114.48,49.47 115.06,48.89 122.66,48.89 123.04,49.27 123.04,49.7 122.88,49.85 122,49.85 121.88,49.98 121.88,50.16 122,50.29 122.88,50.29 v4(123.04,50.46) 123.24,50.46 123.66,50.88 123.97,50.88 v1(124.05,50.79)
  BOTTOM w0.12: v1(124.05,50.79) 123.81,50.79 123.69,50.66 123.69,50.25 123.8,50.13 124.16,50.13 124.18,50.12 124.41,50.12 124.53,50.25 124.53,50.45 124.66,50.58 124.88,50.58 125.01,50.45 125.01,50.19 125.13,50.06 125.35,50.06 125.48,50.19 125.48,50.88 125.35,51 125.04,51 125.03,51.02 124.48,51.02 124.35,51.14 124.35,51.33 124.48,51.45 124.6,51.45 124.73,51.58 124.73,51.75 124.82,51.84 126.26,51.84 126.47,51.63 126.47,50.15 126.69,49.93 126.69,49.76 126.69,49.74 126.69,48.33 126.69,48.31 126.69,47.79 127,47.48 128.42,47.48 128.54,47.35 128.54,46.3 128.42,46.18 127.78,46.18 127.5,46.47 127.06,46.47 126.81,46.22 126.81,46.2 126.39,45.78 126.39,43.31 127.02,42.67 130.88,42.67 131.49,42.06 133.51,42.06 133.72,42.27 133.72,42.47 134.02,42.77 134.43,42.77 134.63,42.56 134.8,42.56 135.07,42.83 135.25,42.83 135.41,42.67 135.41,42.49 135.14,42.22 135.14,42.05 135.31,41.88 135.48,41.88 135.69,42.09 135.86,42.09 136.03,41.92 136.03,41.75 135.82,41.54 135.82,41.38 136.31,40.89 136.31,40.72 136.01,40.43 136.01,40.25 136.17,40.09 136.35,40.09 136.65,40.38 137.32,40.38 137.45,40.26 137.45,40.1 137.37,40.02
M_DQMA#3: length 66.4
  TOP w0.099: 104.58,55.48 104.47,55.6 101.21,55.6 101.09,55.71 100.82,55.71 100.81,55.71 100.8,55.71 100.77,55.69 100.5,55.69 100.22,55.4 U1.C21
  TOP w0.12: 104.58,55.48 105.51,54.55 109.7,54.55 112.44,51.82 112.44,51.07 113.64,49.86 114.91,49.86 115.06,50.01 115.27,50.01 115.38,49.89 115.38,49.41 115.5,49.28 121.84,49.28 v1(121.85,49.3)
  BOTTOM w0.12: v1(121.85,49.3) 121.57,49.02 121.57,48.67 121.34,48.44 121.29,48.44 121.16,48.31 121.16,47.2 121.28,47.08 122.5,47.08 122.73,46.85 122.73,46.72 122.6,46.59 121.28,46.59 121.16,46.48 121.16,46.23 121.28,46.12 123.15,46.12 123.28,45.99 123.28,45.76 123.15,45.63 121.27,45.63 121.16,45.53 121.16,45.29 121.27,45.19 121.61,45.19 v4(121.73,45.06) 121.73,44.94 121.62,44.84 121.62,44.62 121.83,44.42 122,44.42 122.77,45.19 122.95,45.19 123.11,45.03 123.11,44.85 122.34,44.08 122.34,43.91 122.51,43.74 122.68,43.74 123.52,44.58 123.7,44.58 123.86,44.42 123.86,44.24 123.02,43.4 123.02,43.23 123.19,43.06 123.36,43.06 124.25,43.95 124.42,43.95 124.59,43.78 124.59,43.61 123.7,42.72 123.7,42.55 123.87,42.38 124.04,42.38 124.43,42.77 124.6,42.77 124.77,42.61 124.77,42.43 124.37,42.04 124.37,41.87 124.54,41.7 124.71,41.7 125.1,42.09 125.25,42.09 125.44,41.9 125.44,41.75 125.05,41.36 125.05,41.19 125.22,41.02 125.39,41.02 125.78,41.41 125.93,41.41 126.12,41.22 126.12,41.07 125.73,40.68 125.73,40.51 125.9,40.34 126.07,40.34 126.36,40.63 126.51,40.63 126.7,40.44 126.7,40.29 126.41,40 126.41,39.83 126.58,39.66 126.75,39.66 126.83,39.74 127,39.74 127.17,39.57 127.17,39.4 127.09,39.32 127.09,39.15 127.59,38.66 128.04,38.66 128.34,38.37 131.62,38.37 131.75,38.5 131.95,38.5 131.97,38.52 132.06,38.52 132.4,38.85 132.65,38.85 132.66,38.86 132.71,38.86 132.8,38.95 133.13,38.95 133.22,38.86 133.47,38.86 133.63,38.7 133.94,38.7 134.16,38.91 134.16,39.22
M_DQMA#4: length 67
  TOP w0.099: 101.23,61.28 101.56,61.28 101.72,61.44 102.52,61.44 102.79,61.7
  TOP w0.1: 101.23,61.28 100.73,61.28 100.7,61.31 100.42,61.31 100.23,61.13 100.23,61.04 99.88,60.69 99.62,60.69 99.44,60.87 99.44,61.09 99.31,61.21 98.92,61.21 98.8,61.34 98.8,61.56 98.92,61.69 99.23,61.69 U1.E13
  TOP w0.12: 102.79,61.7 105.14,61.7 105.44,62 109.54,62 110.39,62.85 110.54,62.85 110.66,62.73 110.66,62.62 110.78,62.5 110.94,62.5 111.06,62.62 111.06,63.68 111.17,63.79 111.33,63.79 111.45,63.68 111.45,63.66 111.54,63.57 111.54,62.62 111.66,62.5 111.84,62.5 111.96,62.62 111.96,63.19 112.07,63.3 112.32,63.3 112.44,63.19 112.44,62.52 112.56,62.4 112.8,62.4 112.92,62.52 112.92,62.79 113.05,62.91 113.28,62.91 113.4,62.79 113.4,62.47 113.87,62 114.66,62 114.89,62.23 114.89,64.57 v1(114.94,64.62)
  BOTTOM w0.12: v1(114.94,64.62) 115.09,64.47 115.28,64.47 115.41,64.6 115.41,70.89 115.89,71.38 116.97,71.38 120.03,74.44 120.03,74.88 120.05,74.89 120.05,77.61 123.41,80.97 123.41,82.75 v4(123.6,82.95) 123.8,83.14 134.09,83.14 136.95,80.28 136.95,80.2 136.97,80.2 136.97,79.67 136.84,79.56 136.8,79.56 136.68,79.44 136.68,79.19 136.8,79.08 136.84,79.08 136.97,78.95 136.97,78.72 136.84,78.59 136.8,78.59 136.68,78.47 136.68,78.23 136.8,78.11 136.84,78.11 136.97,78 136.97,77.55 137.13,77.38 137.37,77.38
M_DQMA#5: length 66.6
  TOP w0.1: U1.D12 100.06,62.91 100.7,62.91 100.73,62.89 101.2,62.89 101.25,62.91 101.38,63.04 101.72,63.04 101.76,63 101.82,62.99 103.1,62.99
  TOP w0.12: v1(124.55,65.49) 124.55,66 123.93,66.62 110.5,66.62 108.06,64.19 105.27,64.19 104.06,62.99 103.1,62.99
  BOTTOM w0.12: U402.E7 133.96,76.58 133.51,76.13 132.42,76.13 132.38,76.08 131.13,76.08 130.97,75.92 130.97,75.92 130.78,75.72 130.44,75.72 130.31,75.85 130.31,76.18 130.19,76.31 129.96,76.31 129.84,76.18 129.84,76.05 129.71,75.92 129.38,75.92 129.26,76.04 129.26,76.17 129.14,76.29 128.9,76.29 128.78,76.17 128.78,76.04 128.66,75.92 128.42,75.92 128.3,76.04 128.3,76.17 128.18,76.29 127.94,76.29 127.82,76.17 127.82,76.04 127.7,75.92 127.46,75.92 127.34,76.04 127.34,76.17 127.22,76.29 126.98,76.29 126.86,76.17 126.86,76.04 126.74,75.92 126.35,75.92 126.22,76.05 126.22,76.64 126.1,76.77 125.84,76.77 125.71,76.64 125.71,76.37 125.59,76.25 125.18,76.25 125.06,76.12 125.06,75.95 125.18,75.83 125.86,75.83 125.98,75.7 125.98,75.45 125.86,75.32 125.18,75.32 125.06,75.2 125.06,74.96 125.18,74.84 125.59,74.84 125.71,74.72 125.71,73.3 124.65,72.23 124.65,70.95 123.63,69.93 121.43,69.93 121.33,69.83 121.33,69.58 121.46,69.45 123.58,69.45 123.59,69.45 123.7,69.33 123.7,69.09 123.58,68.97 121.52,68.97 121.4,68.84 121.4,68.61 121.52,68.49 122.99,68.49 123.12,68.36 123.12,68.14 122.99,68.01 122.73,68.01 122.61,67.89 v4(122.61,67.62) 122.61,67.43 122.49,67.31 122.18,67.31 122.05,67.43 122.05,67.89 121.93,68.01 121.62,68.01 121.5,67.89 121.5,67.04 121.62,66.92 123.34,66.92 124.36,65.9 124.36,65.68 v1(124.55,65.49)
M_DQMA#6: length 63.5
  TOP w0.1: U1.E3 99.62,69 100,69.37 100.38,69.37 101.41,70.41
  TOP w0.12: 101.41,70.41 101.54,70.53 101.54,71.14 102.52,72.12 102.52,72.9 102.5,72.92 102.5,73.21 102.45,73.27 v1(102.39,73.27) ; v1(118.06,82.19) 118.15,82.09 118.15,81.89 118.74,81.3 133.24,81.3 134.97,79.56 134.97,78.19 U401.D3
  BOTTOM w0.12: v1(118.06,82.19) 116.53,83.72 110.2,83.72 108.57,82.09 v4(108.57,77.11) 108.57,76.5 108.22,76.14 107.95,76.14 107.83,76.27 107.83,76.83 107.7,76.96 107.7,76.97 107.45,76.97 107.34,76.86 107.34,76.39 107.22,76.27 106.99,76.27 106.87,76.39 106.87,76.83 106.74,76.96 106.74,76.97 106.5,76.97 106.38,76.86 106.38,76.39 106.26,76.27 106.03,76.27 105.91,76.39 105.91,76.83 105.78,76.96 105.78,76.97 105.53,76.97 105.42,76.86 105.42,76.39 105.3,76.27 105.07,76.27 104.95,76.39 104.95,76.83 104.82,76.96 104.82,76.97 104.57,76.97 104.47,76.86 104.47,76.39 104.34,76.27 104.11,76.27 103.99,76.39 103.99,76.83 103.86,76.96 103.86,76.97 103.62,76.97 103.5,76.86 103.5,76.39 103.38,76.27 103.07,76.27 102.95,76.39 102.95,76.94 102.82,77.06 102.52,77.06 102.39,76.94 102.39,75.73 102.52,75.61 103.44,75.61 103.57,75.48 103.57,75.23 103.44,75.11 102.52,75.11 102.39,74.98 102.39,74.58 102.52,74.45 103.45,74.45 103.57,74.34 103.57,74.1 103.45,73.97 102.52,73.97 102.39,73.85 v1(102.39,73.27)
M_DQMA#7: length 63.9
  TOP w0.1: 99.02,69.64 99.02,69.42 98.55,68.95 U1.F4
  TOP w0.12: 99.02,69.64 99.02,69.93 99.27,70.18 99.27,70.19 100.52,71.44 100.82,71.44 v1(101.82,72.44) ; v1(118.03,75.42) 119.37,76.76 120.02,76.76 120.17,76.61 120.67,76.61 120.82,76.76 126.39,76.76 126.97,77.34 130.09,77.34 130.38,77.64 131.06,77.64 131.76,76.94 132.12,76.94 132.13,76.93 134.31,76.93 134.52,76.72 134.52,76.43 134.31,76.22 134.1,76.22 133.8,75.93 133.8,74.82 134.01,74.61 134.32,74.61 134.73,75.03 135.24,75.03 136.47,76.27 136.47,76.34 136.72,76.58 137.35,76.58 137.37,76.58
  BOTTOM w0.12: v1(118.03,75.42) 118.01,75.43 117.38,75.43 117.32,75.5 117.31,75.5 117.19,75.62 117.19,75.63 117.05,75.77 115.83,75.77 115.82,75.78 115.66,75.78 115.16,76.28 113.52,76.28 113.16,75.92 111.72,75.92 111.27,75.48 111.27,73.13 111.7,72.7 111.7,70.55 111.06,69.91 107.57,69.91 106.52,70.96 106.52,71.49 106.69,71.66 106.69,71.88 106.82,72 107.05,72 107.68,72.64 107.68,72.77 107.8,72.89 107.8,75.54 107.67,75.67 v4(107.55,75.67) 107.41,75.67 107.29,75.54 107.29,75.5 107.16,75.38 106.94,75.38 106.81,75.5 106.81,75.75 106.69,75.87 106.45,75.87 106.33,75.75 106.33,75.5 106.2,75.38 105.97,75.38 105.85,75.5 105.85,75.75 105.72,75.87 105.5,75.87 105.37,75.75 105.37,75.5 105.25,75.38 105.02,75.38 104.89,75.5 104.89,75.72 104.77,75.84 104.5,75.84 103.98,75.33 103.98,73.91 102.52,72.44 v1(101.82,72.44)
M_MAA0: length 108.9
  TOP w0.097: v1(137.03,64.23) 137.04,64.23 137.04,64.16 136.54,63.66 136.53,63.66 136.51,63.65 135.7,63.65 134.76,62.7 134.74,62.7 134.73,62.7 131.78,62.7 v1(131.59,62.51) 131.75,62.51 131.88,62.38 131.88,62.11 131.51,61.66 131.26,61.34 131.22,61.29 131.22,61.28 130.52,60.41 130.46,60.35 130.46,58.73 130.34,58.62 v4(130.13,58.62) 129.99,58.62 129.83,58.45 129.83,57.86 v1(130,57.7) 130.09,57.79 130.09,57.85 130.19,57.95 130.32,57.95 130.41,57.85 130.41,57.37 130.31,57.26 129.93,57.26 129.85,57.19 129.85,57.03 129.93,56.96 130.38,56.96 130.47,56.88 130.48,56.85 130.5,56.79 130.5,56.76 130.38,56.64 129.96,56.64 129.89,56.57 129.89,56 129.94,55.89 131.43,54.4 131.59,54.4 132.01,53.98 132.69,53.98 133.15,53.51 134.05,53.51 135.63,51.93 136,51.93 136.34,51.93 137.04,51.24 137.36,51.24 v1(137.64,50.95) 137.45,50.95 137.37,50.88 137.37,50.65 137.48,50.55 138.03,50.55 138.12,50.45 138.12,50.34 138.03,50.24 137.7,50.24 137.6,50.14 137.6,50.03 137.43,49.86 137.43,49.83 137.38,49.79 137.16,49.56 136.99,49.56 136.9,49.65 136.9,49.85 136.81,49.94 136.67,49.94 136.58,49.85 136.58,47.83 136.66,47.75 136.72,47.75 136.81,47.66 136.81,47.54 136.72,47.45 136.64,47.45 136.58,47.38 136.58,47.21 136.64,47.15 136.74,47.15 136.82,47.06 136.82,46.87 136.72,46.77 136.68,46.77 136.58,46.67 136.58,46.46 136.68,46.36 136.84,46.36 137.04,46.16 137.29,46.16 137.37,46.24 137.37,46.41 ; v1(130.06,66.47) 131.07,66.47 131.32,66.22 131.34,66.22 131.34,66.21 131.69,66.21 131.69,66.22 133.59,66.22 134.16,66.78 134.16,66.99 134.71,67.54 134.71,69.31 134.58,69.44 134.57,69.44 134.51,69.51 134.51,69.52 134.45,69.57 134.45,69.7 134.71,69.96 134.71,70.09 134.59,70.21 134.36,70.21 134.35,70.22 134.21,70.22 U401.N3
  TOP w0.17: U1.K17 95.35,58.8 v1(95.15,59)
  BOTTOM w0.097: U201.N3 135.13,47.38 135.31,50.83 135.54,51.06 135.88,51.06 135.88,51.06 137.56,51.06 137.66,50.97 137.66,50.95 v1(137.64,50.95) ; v1(131.59,62.51) 130.04,64.06 130.04,65.64 129.98,65.7 129.98,66.39 v1(130.06,66.47) ; 137.37,70.17 137.37,70.14 136.83,69.61 136.83,67.55 138.19,66.19 138.19,65.95 138.19,65.95 138.19,65.71 138.19,65.71 138.19,65.61 138.18,65.6 138.19,65.59 138.19,65.55 138.18,65.55 137.84,65.2 137.72,65.2 137.62,65.3 137.52,65.3 137.4,65.17 137.4,65.01 137.49,64.91 137.49,64.77 137.39,64.67 137.21,64.67 137.09,64.8 137.09,64.81 136.98,64.92 136.82,64.92 136.71,64.81 136.71,64.75 136.67,64.7 136.67,64.36 136.79,64.24 137.03,64.24 v1(137.03,64.23)
  BOTTOM w0.1: 100.35,58.18 98.21,58.18 98.19,58.2 98.19,58.2 97.78,58.6 97.75,58.6 97.7,58.65 96.56,58.65 96.5,58.6 96.06,58.6 95.78,58.33 95.25,58.33 95.15,58.42 v1(95.15,59)
  BOTTOM w0.2: v1(130,57.7) 128.23,57.7 127.52,56.99 127.52,56.97 127.26,56.7 125.6,56.7 125.5,56.8 125.5,57.01 125.42,57.09 124.79,57.09 124.7,57.01 124.7,56.8 124.6,56.7 124.12,56.7 124.03,56.8 124.03,56.99 123.93,57.09 123.31,57.09 123.21,56.99 123.21,56.8 123.11,56.7 122.4,56.7 122.3,56.8 122.3,57.01 122.21,57.09 121.59,57.09 121.5,57.01 121.5,56.8 121.4,56.7 120.8,56.7 120.7,56.8 120.7,56.98 120.6,57.09 120,57.09 119.9,56.98 119.9,56.81 119.8,56.72 119.21,56.72 119.11,56.81 119.11,57.02 119.03,57.09 118.38,57.09 118.31,57.02 118.31,56.8 118.22,56.7 117.59,56.7 117.5,56.8 117.5,56.97 117.4,57.07 116.8,57.07 116.7,56.97 116.7,56.8 116.6,56.7 116.02,56.7 115.92,56.8 115.92,57.01 115.92,57.01 115.84,57.09 115.21,57.09 115.12,57.01 115.12,56.8 115.02,56.7 114.4,56.7 114.3,56.8 114.3,56.99 114.2,57.09 113.75,57.09 113.65,56.99 113.65,56.8 113.56,56.7 113.06,56.7 112.98,56.78 112.98,56.98 112.88,57.08 112.39,57.08 112.29,56.98 112.29,56.81 112.19,56.72 111.87,56.72 111.77,56.81 111.77,57 111.67,57.09 111.23,57.09 111.14,57 111.14,56.8 111.04,56.7 110.56,56.7 110.46,56.81 110.46,56.99 110.36,57.09 109.88,57.09 109.78,56.99 109.78,56.82 109.66,56.7 109.13,56.7 109.03,56.8 109.03,57.02 108.95,57.09 108.62,57.09 108.52,56.99 108.52,56.81 108.41,56.71 108,56.71 107.91,56.81 107.91,56.95 107.81,57.05 107.25,57.05 107.15,56.95 107.15,56.8 107.05,56.7 106.74,56.7 106.35,57.09 106.34,57.09 106.18,57.26 106.18,57.26 105.62,57.82 102.37,57.82 101.92,58.26 100.43,58.26 100.35,58.18
